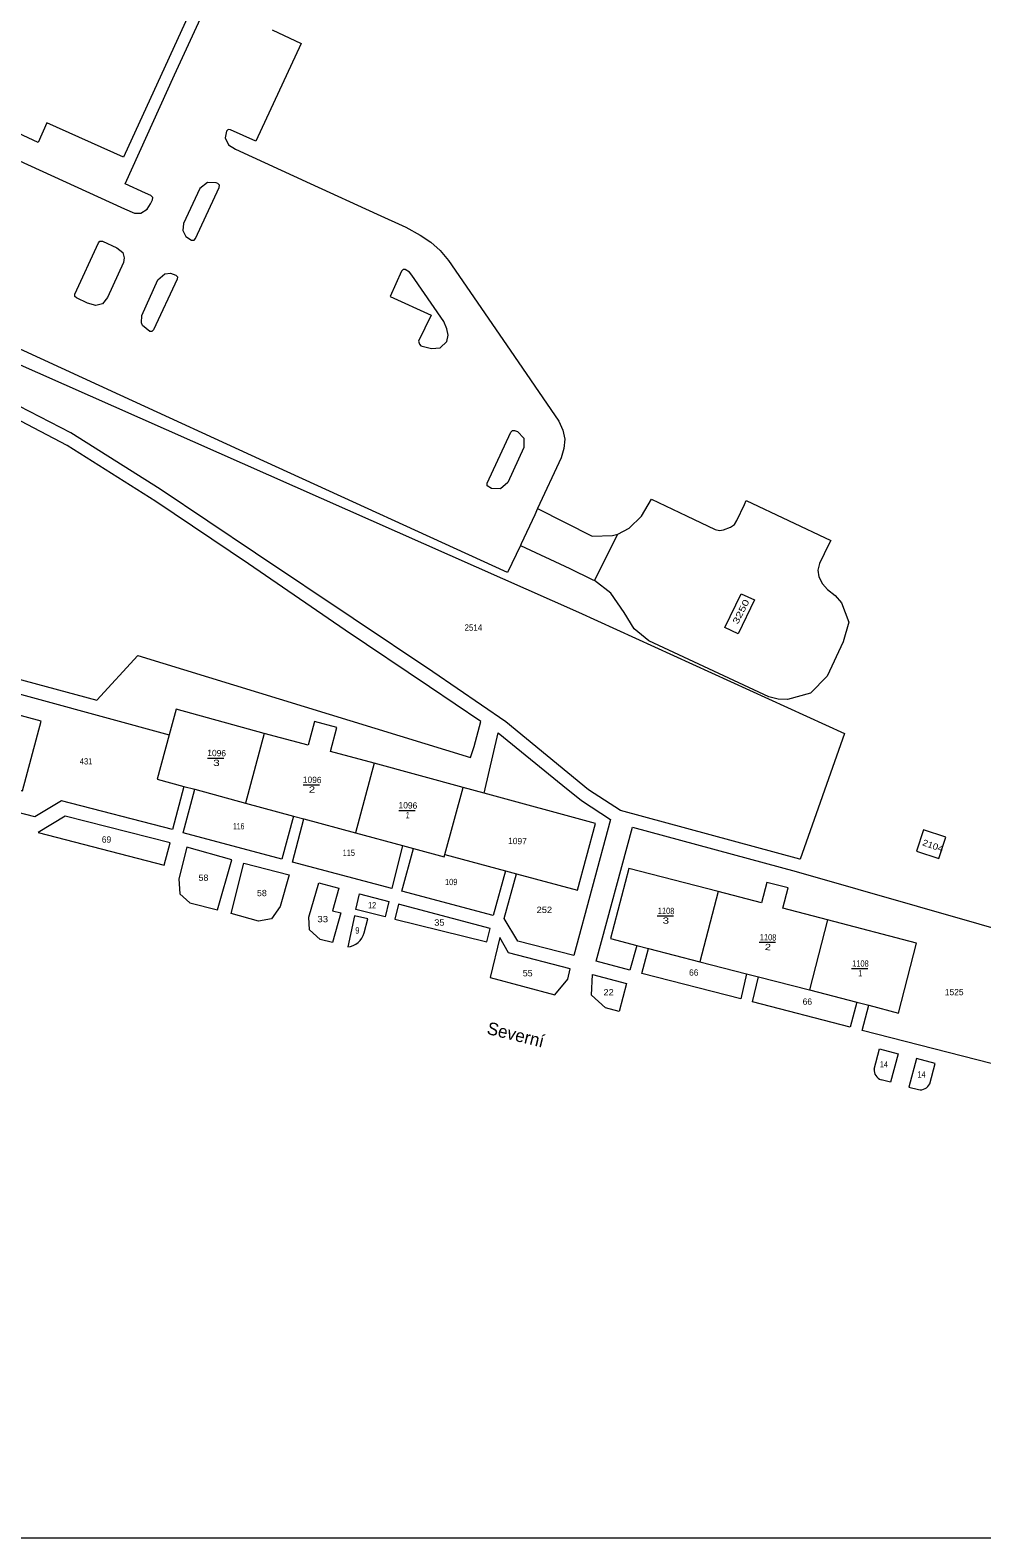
# Model space of a CAD drawing. Extents: x -843400 to -842830, y -1002860 to -1002082.
# Drawn here: x -843248.8 to -843097.6, y -1002860 to -1002620.7 of the extents above; entities that cross this region are included whole.
import ezdxf
from ezdxf.enums import TextEntityAlignment as Align

# ---------------------------------------------------------------- set-up
doc = ezdxf.new("R2010")
doc.units = 0
doc.header["$LTSCALE"] = 0.4
doc.layers.add('20', color=7, linetype='Continuous')
for name, color, linetype, lineweight in [('32', 7, 'Continuous', 13), ('35', 7, 'Continuous', 13), ('36', 7, 'Continuous', 13), ('38', 7, 'Continuous', 13), ('43', 7, 'Continuous', 13), ('44', 7, 'Continuous', 13)]:
    doc.layers.add(name, color=color, linetype=linetype, lineweight=lineweight)

msp = doc.modelspace()

# ---------------------------------------------------------------- linework, layer by layer
at = {"layer": '32'}
msp.add_lwpolyline([(-843159.15, -1002708.03), (-843155.43, -1002700.64), (-843153.6, -1002699.71), (-843151.64, -1002697.82), (-843150.1, -1002695.08), (-843144.52, -1002697.73), (-843139.97, -1002699.93), (-843139.3, -1002700.07), (-843138.62, -1002699.96), (-843137.53, -1002699.57), (-843136.91, -1002699.15), (-843136.53, -1002698.5), (-843135.3, -1002695.97), (-843135.02, -1002695.34), (-843121.59, -1002701.65), (-843121.9, -1002702.27), (-843123.4, -1002705.33), (-843123.65, -1002706.38), (-843123.49, -1002707.45), (-843122.9, -1002708.53), (-843122.1, -1002709.47), (-843120.92, -1002710.42), (-843119.9, -1002711.55), (-843118.75, -1002714.62), (-843119.61, -1002717.78), (-843122.18, -1002723.2), (-843124.81, -1002725.92), (-843128.45, -1002726.91), (-843129.96, -1002726.85), (-843131.44, -1002726.5), (-843150.48, -1002717.62), (-843152.83, -1002715.71), (-843154.42, -1002713.12), (-843156.51, -1002710.04)], close=True, dxfattribs=at)
at = {"layer": '35'}
for p, q in [((-843220.586, -1002736.207), (-843217.99, -1002736.207)), ((-843205.412, -1002740.454), (-843202.816, -1002740.454)), ((-843190.206, -1002744.507), (-843187.61, -1002744.507)), ((-843149.198, -1002761.257), (-843146.602, -1002761.257)), ((-843132.996, -1002765.451), (-843130.4, -1002765.451)), ((-843118.326, -1002769.613), (-843115.73, -1002769.613))]:
    msp.add_line(p, q, dxfattribs=at)
at = {"layer": '36'}
for points in [[(-843251.05, -1002641.12), (-843233.78, -1002649.04), (-843232.2, -1002649.72), (-843231.2, -1002649.72), (-843230.2, -1002649.08), (-843229.67, -1002648.22), (-843229.34, -1002647.57), (-843229.3, -1002647.21), (-843229.58, -1002646.92), (-843230.46, -1002646.51), (-843233.66, -1002645.03), (-843225.82, -1002627.76), (-843214.48, -1002603.05)], [(-843210.31, -1002620.62), (-843205.72, -1002622.79), (-843212.9, -1002638.28), (-843216.96, -1002636.49), (-843217.32, -1002636.44), (-843217.59, -1002636.7), (-843217.77, -1002637.75), (-843217.29, -1002638.85), (-843216.18, -1002639.53), (-843204.32, -1002644.98), (-843193.66, -1002649.87), (-843189.11, -1002651.94), (-843186.81, -1002653.19), (-843185.15, -1002654.33), (-843183.64, -1002655.65), (-843182.3, -1002657.21), (-843173.12, -1002670.58), (-843164.81, -1002682.73), (-843164.14, -1002684.14), (-843163.82, -1002685.59), (-843163.98, -1002687.08), (-843164.41, -1002688.56), (-843168.17, -1002696.59), (-843168.63, -1002697.58), (-843170.8, -1002702.22), (-843170.91, -1002702.46), (-843172.95, -1002706.75), (-843211.66, -1002689.05), (-843234.47, -1002678.6), (-843253.1, -1002670.04)], [(-843168.17, -1002696.59), (-843159.49, -1002700.97), (-843156.29, -1002700.89), (-843155.43, -1002700.64)], [(-843170.91, -1002702.46), (-843163.04, -1002706.1), (-843159.52, -1002707.84), (-843159.15, -1002708.03)]]:
    msp.add_lwpolyline(points, dxfattribs=at)
for points in [[(-843218.74, -1002645.64), (-843218.71, -1002645.26), (-843218.95, -1002645.01), (-843219.21, -1002644.87), (-843220.62, -1002644.83), (-843221.82, -1002645.79), (-843224.42, -1002651.37), (-843224.53, -1002652.43), (-843224.05, -1002653.41), (-843223.12, -1002653.99), (-843222.72, -1002654.01), (-843222.49, -1002653.74)], [(-843241.66, -1002662.54), (-843237.92, -1002654.4), (-843237.68, -1002654.16), (-843237.3, -1002654.17), (-843235, -1002655.19), (-843234.07, -1002655.95), (-843233.83, -1002656.81), (-843233.94, -1002657.55), (-843236.48, -1002663.1), (-843237.28, -1002664.08), (-843238.36, -1002664.35), (-843239.68, -1002664), (-843241.43, -1002663.17), (-843241.69, -1002662.92)], [(-843225.4, -1002660.17), (-843229.17, -1002668.23), (-843229.42, -1002668.51), (-843229.78, -1002668.49), (-843230.91, -1002667.55), (-843231.08, -1002667.1), (-843231.01, -1002665.94), (-843228.49, -1002660.29), (-843227.4, -1002659.33), (-843226.48, -1002659.22), (-843225.61, -1002659.55), (-843225.36, -1002659.81)], [(-843191.6, -1002662.95), (-843185.09, -1002665.91), (-843187.09, -1002670.02), (-843186.95, -1002670.5), (-843186.69, -1002670.74), (-843185.03, -1002671.21), (-843183.67, -1002671.06), (-843182.57, -1002670.1), (-843182.36, -1002669.06), (-843182.56, -1002668.07), (-843183.07, -1002666.9), (-843188.14, -1002659.54), (-843188.54, -1002659.08), (-843189.18, -1002658.67), (-843189.52, -1002658.66), (-843189.8, -1002658.93)], [(-843172.41, -1002684.45), (-843172.17, -1002684.18), (-843171.82, -1002684.18), (-843171.38, -1002684.38), (-843170.34, -1002685.44), (-843170.33, -1002686.88), (-843172.88, -1002692.46), (-843174.07, -1002693.48), (-843175.51, -1002693.39), (-843176.17, -1002692.97), (-843176.17, -1002692.56)], [(-843138.43, -1002715.47), (-843135.82, -1002710.11), (-843133.71, -1002711.09), (-843136.3, -1002716.48)]]:
    msp.add_lwpolyline(points, close=True, dxfattribs=at)
at = {"layer": '38'}
for p, q in [((-843211.59, -1002732.29), (-843214.57, -1002743.35)), ((-843194.12, -1002737.04), (-843197.1, -1002748.08)), ((-843224.37, -1002740.7), (-843222.63, -1002741.17)), ((-843182.88, -1002751.51), (-843180.01, -1002740.88)), ((-843206.92, -1002745.42), (-843205.3, -1002745.86)), ((-843189.63, -1002750.1), (-843187.89, -1002750.57)), ((-843173.277, -1002754.106), (-843171.537, -1002754.576)), ((-843139.51, -1002757.39), (-843142.41, -1002768.53)), ((-843122.11, -1002761.9), (-843125, -1002773.02)), ((-843152.4, -1002765.94), (-843150.53, -1002766.42)), ((-843135, -1002770.44), (-843133.06, -1002770.94)), ((-843117.48, -1002774.96), (-843115.58, -1002775.45))]:
    msp.add_line(p, q, dxfattribs=at)
for points in [[(-843276.99, -1002555.6), (-843271.63, -1002558.06), (-843267.9, -1002550.12), (-843233.22, -1002566.07), (-843229.49, -1002557.91), (-843217.51, -1002563.41), (-843214.18, -1002568.18), (-843216.63, -1002573.61), (-843205.49, -1002578.73), (-843233.93, -1002640.83), (-843246.1, -1002635.37), (-843247.52, -1002638.46), (-843254.81, -1002635.1), (-843253.51, -1002632), (-843281.23, -1002619.2), (-843296.36, -1002612.22), (-843281.484, -1002579.845), (-843280.65, -1002578.03), (-843286.12, -1002575.52)], [(-843176.633, -1002741.799), (-843180.01, -1002740.88), (-843194.12, -1002737.04), (-843201.07, -1002735.15), (-843200.06, -1002731.36), (-843203.6, -1002730.4), (-843204.62, -1002734.18), (-843211.59, -1002732.29), (-843225.59, -1002728.47), (-843226.684, -1002732.515)]]:
    msp.add_lwpolyline(points, dxfattribs=at)
msp.add_lwpolyline([(-843106.86, -1002747.6), (-843107.97, -1002751), (-843104.42, -1002752.15), (-843103.31, -1002748.76)], close=True, dxfattribs=at)
at = {"layer": '43'}
msp.add_line((-843197.243, -1002761.253), (-843198.336, -1002766.199), dxfattribs=at)
for points in [[(-843126.476, -1002752.253), (-843126.528, -1002752.238), (-843154.983, -1002744.549), (-843160.073, -1002741.24), (-843173.21, -1002730.47), (-843184.83, -1002722.53), (-843197.49, -1002714.05), (-843212.96, -1002703.67), (-843228.1, -1002693.51), (-843242.33, -1002684.6), (-843253.86, -1002678.65), (-843263.49, -1002674.86), (-843275.48, -1002670.79), (-843272.718, -1002665.086), (-843272.254, -1002664.121), (-843161.67, -1002713.05), (-843119.43, -1002732.33)], [(-843177.187, -1002730.405), (-843185.333, -1002724.896), (-843198.75, -1002715.9), (-843214.09, -1002705.37), (-843228.82, -1002695.48), (-843242.91, -1002686.57), (-843254.55, -1002680.51), (-843265, -1002676.44), (-843276.39, -1002672.52), (-843289.772, -1002693.597), (-843294.56, -1002711.84), (-843238.17, -1002726.99), (-843231.68, -1002719.95), (-843178.83, -1002736.1), (-843178.26, -1002734.36)], [(-843267.25, -1002721.46), (-843226.684, -1002732.515), (-843228.59, -1002739.56), (-843224.37, -1002740.7), (-843226.15, -1002747.56), (-843243.8, -1002742.97), (-843248.04, -1002745.54), (-843255.63, -1002743.57), (-843254.75, -1002740.16), (-843249.99, -1002741.43), (-843247.03, -1002730.33), (-843261.17, -1002726.55), (-843268.12, -1002724.69)], [(-843171.537, -1002754.576), (-843161.83, -1002757.2), (-843158.96, -1002746.61), (-843176.633, -1002741.799), (-843174.44, -1002732.2), (-843164.164, -1002740.575), (-843161.186, -1002742.953), (-843156.57, -1002745.953), (-843162.42, -1002767.54), (-843171.33, -1002765.29), (-843173.46, -1002761.69)], [(-843214.57, -1002743.35), (-843206.92, -1002745.42), (-843208.8, -1002752.27), (-843224.45, -1002748.08), (-843222.63, -1002741.17)], [(-843227.471, -1002753.216), (-843226.548, -1002749.656), (-843243.198, -1002745.412), (-843247.498, -1002748.019)], [(-843197.1, -1002748.08), (-843189.63, -1002750.1), (-843191.3, -1002756.9), (-843207.11, -1002752.71), (-843205.3, -1002745.86)], [(-843219.02, -1002760.29), (-843216.719, -1002752.364), (-843223.888, -1002750.334), (-843225.161, -1002755.384), (-843224.99, -1002757.758), (-843223.395, -1002759.17)], [(-843175.201, -1002761.224), (-843189.73, -1002757.34), (-843187.89, -1002750.57), (-843182.99, -1002751.9), (-843182.88, -1002751.51), (-843173.277, -1002754.106)], [(-843216.85, -1002760.87), (-843214.82, -1002752.87), (-843207.61, -1002754.75), (-843209.07, -1002759.75), (-843210.42, -1002761.71), (-843212.51, -1002762.12)], [(-843202.68, -1002765), (-843204.42, -1002763.46), (-843204.53, -1002761.45), (-843202.94, -1002756), (-843199.76, -1002756.88), (-843200.75, -1002760.48), (-843199.44, -1002760.76), (-843200.77, -1002765.5)], [(-843197.024, -1002760.25), (-843196.48, -1002757.76), (-843191.791, -1002758.998), (-843192.356, -1002761.41)], [(-843190.244, -1002759.406), (-843190.835, -1002761.788), (-843176.21, -1002765.391), (-843175.691, -1002763.249)], [(-843175.729, -1002771.067), (-843165.429, -1002773.775), (-843163.37, -1002771.31), (-843162.97, -1002769.69), (-843172.77, -1002767.11), (-843174.183, -1002764.677)], [(-843135, -1002770.44), (-843135.89, -1002774.42), (-843151.59, -1002770.39), (-843150.53, -1002766.42), (-843142.41, -1002768.53)], [(-843155.236, -1002776.45), (-843157.402, -1002775.883), (-843159.61, -1002773.85), (-843159.44, -1002770.59), (-843154.067, -1002771.985)], [(-843125, -1002773.02), (-843117.48, -1002774.96), (-843118.52, -1002778.91), (-843134.05, -1002774.93), (-843133.06, -1002770.94)]]:
    msp.add_lwpolyline(points, close=True, dxfattribs=at)
for points in [[(-843091.57, -1002785.84), (-843116.6, -1002779.43), (-843115.58, -1002775.45), (-843110.85, -1002776.68), (-843107.97, -1002765.57), (-843122.11, -1002761.9), (-843129.21, -1002760.06), (-843128.37, -1002756.82), (-843131.78, -1002755.97), (-843132.61, -1002759.18), (-843139.51, -1002757.39), (-843153.68, -1002753.72), (-843156.57, -1002764.86), (-843152.4, -1002765.94), (-843153.51, -1002769.86), (-843158.88, -1002768.46), (-843153.11, -1002747.17), (-843127.075, -1002754.205), (-843040.429, -1002779.029)], [(-843195.728, -1002763.949), (-843195.16, -1002761.72), (-843197.243, -1002761.253)], [(-843114.713, -1002785.587), (-843113.88, -1002782.363), (-843110.9, -1002783.14)], [(-843110.9, -1002783.14), (-843112.093, -1002787.671), (-843113.619, -1002787.277)], [(-843107.999, -1002783.904), (-843109.192, -1002788.435), (-843107.671, -1002788.844)], [(-843105.886, -1002787.912), (-843105.023, -1002784.695), (-843107.999, -1002783.904)]]:
    msp.add_lwpolyline(points, dxfattribs=at)
for centre, radius, start, end in [((-843198.6415, -1002763.2073), 3.0069, 275.83701, 345.71005), ((-843113.0651, -1002785.7202), 1.6528, 175.39198, 250.42189), ((-843107.3856, -1002787.216), 1.6528, 260.06946, 335.09936)]:
    msp.add_arc(centre, radius, start, end, dxfattribs=at)
at = {"layer": '44'}
msp.add_lwpolyline([(-842830.097, -1002859.997), (-842830.097, -1002081.989), (-843400.094, -1002081.989), (-843400.094, -1002859.997)], close=True, dxfattribs=at)

# ---------------------------------------------------------------- texts
at = {"layer": '20'}
msp.add_text('Severní', height=2, rotation=346.137, dxfattribs=at).set_placement((-843176.35, -1002779.975))
at = {"layer": '35'}
for s, rotation, width, p in [('3250', 63.069, 1.4, (-843135.43, -1002713.1955)), ('3', 358.734, 1.4, (-843219.1915, -1002737.4595)), ('2', 358.734, 1.35, (-843204.017, -1002741.7063)), ('1', 358.734, 0.7, (-843188.8115, -1002745.7598)), ('2104', 340.639, 1.15, (-843105.5428, -1002750.5861)), ('1108', 358.734, 0.85, (-843147.769, -1002760.9608)), ('3', 358.734, 1.4, (-843147.8045, -1002762.5095)), ('1108', 358.734, 0.85, (-843131.567, -1002765.1538)), ('2', 358.734, 1.35, (-843131.602, -1002766.7033)), ('1108', 358.734, 0.85, (-843116.8975, -1002769.3158)), ('1', 358.734, 0.7, (-843116.9315, -1002770.8648))]:
    msp.add_text(s, height=1, rotation=rotation, dxfattribs=dict(at, width=width)).set_placement(p, align=Align.CENTER)
for s, p in [('1096', (-843219.1575, -1002735.9101)), ('1096', (-843203.9835, -1002740.1571)), ('1096', (-843188.776, -1002744.2101)), ('1097', (-843171.377, -1002749.8806))]:
    msp.add_text(s, height=1, rotation=358.734, dxfattribs=at).set_placement(p, align=Align.CENTER)
at = {"layer": '43'}
for s, width, p in [('2514', 0.95, (-843179.781, -1002715.986)), ('431', 0.9, (-843240.897, -1002737.224)), ('116', 0.65, (-843216.546, -1002747.534)), ('115', 0.7, (-843199.133, -1002751.74)), ('58', 1.05, (-843222.024, -1002755.701)), ('109', 0.85, (-843182.872, -1002756.38)), ('58', 1.05, (-843212.748, -1002758.129)), ('12', 0.8, (-843195.105, -1002760.054)), ('252', 1.1, (-843168.32, -1002760.793)), ('33', 1.15, (-843203.154, -1002762.266)), ('9', 0.9, (-843197.131, -1002764.072)), ('35', 1.1, (-843184.586, -1002762.814)), ('55', 1.05, (-843170.522, -1002770.861)), ('22', 1.1, (-843157.707, -1002773.89)), ('14', 0.7, (-843113.809, -1002785.325)), ('14', 0.7, (-843107.834, -1002786.925))]:
    msp.add_text(s, height=1, dxfattribs=dict(at, width=width)).set_placement(p)
for s, p in [('69', (-843237.38, -1002749.635)), ('66', (-843144.11, -1002770.753)), ('1525', (-843103.483, -1002773.86)), ('66', (-843126.068, -1002775.366))]:
    msp.add_text(s, height=1, dxfattribs=at).set_placement(p)

doc.saveas('drawing.dxf')
